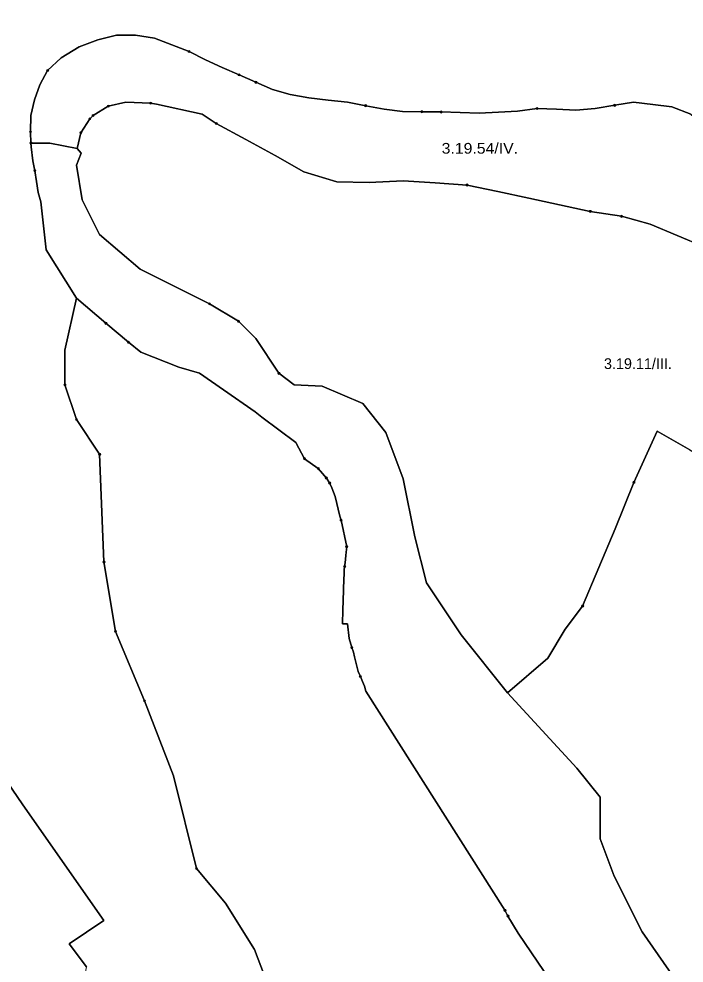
# Model space of a CAD drawing. Extents: x -650455 to -642254, y -1075222 to -1066610.
# Drawn here: x -647324 to -646705, y -1071216 to -1070337 of the extents above; entities that cross this region are included whole.
import ezdxf
from ezdxf.enums import TextEntityAlignment as Align

# ---------------------------------------------------------------- set-up
doc = ezdxf.new("R2010")
doc.units = 0
doc.header["$LTSCALE"] = 4
doc.header["$PDMODE"] = 32
doc.header["$PDSIZE"] = 2
for name, color, linetype, lineweight in [('1', 7, 'Continuous', 25), ('11', 7, 'Continuous', 13), ('12', 7, 'Continuous', 13), ('13', 7, 'Continuous', 13), ('14', 7, 'Continuous', 13), ('15', 7, 'Continuous', 13)]:
    doc.layers.add(name, color=color, linetype=linetype, lineweight=lineweight)
doc.layers.add('2', color=7, linetype='Continuous')

msp = doc.modelspace()

# ---------------------------------------------------------------- linework, layer by layer
at = {"layer": '1'}
for points in [[(-647811.031, -1070119.811), (-647804.895, -1070123.56), (-647767.192, -1070139.719), (-647729.489, -1070139.719), (-647691.786, -1070161.263), (-647681.013, -1070188.194), (-647633.884, -1070234.65), (-647628.498, -1070288.512), (-647606.954, -1070347.759), (-647601.567, -1070433.938), (-647585.409, -1070514.73), (-647558.478, -1070606.295), (-647547.706, -1070654.771), (-647515.389, -1070730.177), (-647460.18, -1070837.227), (-647390.16, -1070966.495), (-647320.14, -1071068.832), (-647244.734, -1071176.555), (-647277.051, -1071198.1), (-647260.893, -1071219.644)], [(-647140.112, -1070434.285), (-647153.326, -1070425.707), (-647195.752, -1070416.202), (-647201.316, -1070415.275), (-647224.499, -1070414.232), (-647240.728, -1070418.173), (-647254.869, -1070426.866), (-647257.883, -1070429.88), (-647266.229, -1070442.863), (-647269.54, -1070457.526), (-647294.977, -1070452.484), (-647312.695, -1070452.484), (-647313.114, -1070441.961), (-647312.695, -1070426.797), (-647309.341, -1070412.193), (-647304.589, -1070398.148), (-647297.182, -1070384.941), (-647284.464, -1070373.132), (-647267.834, -1070363), (-647250.504, -1070356.361), (-647233.175, -1070351.959), (-647215.286, -1070351.889), (-647197.817, -1070354.894), (-647165.534, -1070367.192), (-647150.161, -1070374.949), (-647134.648, -1070382.006), (-647118.996, -1070388.924), (-647103.204, -1070395.842), (-647087.831, -1070402.62), (-647071.34, -1070407.302), (-647053.87, -1070410.446), (-647035.842, -1070412.473), (-647018.093, -1070414.499), (-647001.043, -1070417.644), (-646983.854, -1070420.788), (-646966.664, -1070422.954), (-646948.775, -1070423.304), (-646930.747, -1070423.513), (-646912.999, -1070424.002), (-646895.25, -1070424.491)], [(-646877.361, -1070423.583), (-646895.25, -1070424.491), (-646912.999, -1070424.002), (-646930.747, -1070423.513), (-646948.775, -1070423.304), (-646966.664, -1070422.954), (-646983.854, -1070420.788), (-647001.043, -1070417.644), (-647018.093, -1070414.499), (-647035.842, -1070412.473), (-647053.87, -1070410.446), (-647071.34, -1070407.302), (-647087.831, -1070402.62), (-647103.204, -1070395.842), (-647118.996, -1070388.924), (-647134.648, -1070382.006), (-647150.161, -1070374.949), (-647165.534, -1070367.192), (-647197.817, -1070354.894), (-647215.286, -1070351.889), (-647233.175, -1070351.959), (-647250.504, -1070356.361), (-647267.834, -1070363), (-647284.464, -1070373.132), (-647297.182, -1070384.941), (-647304.589, -1070398.148), (-647309.341, -1070412.193), (-647312.695, -1070426.797), (-647313.114, -1070441.961), (-647312.695, -1070452.484), (-647312.555, -1070456.006), (-647311.018, -1070468.933), (-647309.061, -1070478.227), (-647307.524, -1070488.359), (-647306.126, -1070498.491), (-647303.575, -1070507.298), (-647298.596, -1070551.76), (-647270.318, -1070596.869), (-647281.091, -1070645.345), (-647281.091, -1070677.662)], [(-646966, -1070765.187), (-646982.158, -1070722.098), (-647003.703, -1070695.167), (-647041.406, -1070679.008), (-647067.632, -1070677.48), (-647081.803, -1070666.889), (-647103.347, -1070634.572), (-647119.506, -1070618.414), (-647146.437, -1070602.256), (-647211.071, -1070569.939), (-647248.774, -1070537.621), (-647264.932, -1070505.305), (-647270.318, -1070472.988), (-647265.926, -1070462.007), (-647269.54, -1070457.526), (-647266.229, -1070442.863), (-647257.883, -1070429.88), (-647254.869, -1070426.866), (-647240.728, -1070418.173), (-647224.499, -1070414.232), (-647201.316, -1070415.275), (-647195.752, -1070416.202), (-647153.326, -1070425.707), (-647140.112, -1070434.285), (-647112.756, -1070449.238), (-647085.399, -1070464.192), (-647058.506, -1070479.145), (-647027.904, -1070488.534), (-646997.766, -1070489.346), (-646966.005, -1070487.607), (-646936.33, -1070489.578), (-646906.655, -1070491.548), (-646877.908, -1070497.692), (-646849.161, -1070503.835), (-646791.898, -1070516.123), (-646762.919, -1070520.643), (-646736.258, -1070527.946), (-646710.988, -1070538.494), (-646685.95, -1070549.043)], [(-646895.25, -1070424.491), (-646877.361, -1070423.583), (-646859.613, -1070422.675), (-646841.444, -1070420.229), (-646823.276, -1070420.998), (-646805.248, -1070421.766), (-646787.22, -1070420.299), (-646769.192, -1070417.294), (-646751.583, -1070414.289), (-646733.694, -1070416.456), (-646716.085, -1070418.622), (-646698.336, -1070425.54), (-646690.65, -1070432.527), (-646682.529, -1070440.373)], [(-646698.336, -1070425.54), (-646716.085, -1070418.622), (-646733.694, -1070416.456), (-646751.583, -1070414.289), (-646769.192, -1070417.294), (-646787.22, -1070420.299), (-646805.248, -1070421.766), (-646823.276, -1070420.998), (-646841.444, -1070420.229), (-646859.613, -1070422.675), (-646877.361, -1070423.583)], [(-646685.95, -1070549.043), (-646710.988, -1070538.494), (-646736.258, -1070527.946), (-646762.919, -1070520.643), (-646791.898, -1070516.123), (-646849.161, -1070503.835), (-646877.908, -1070497.692), (-646906.655, -1070491.548), (-646936.33, -1070489.578), (-646966.005, -1070487.607), (-646997.766, -1070489.346), (-647027.904, -1070488.534), (-647058.506, -1070479.145), (-647085.399, -1070464.192), (-647112.756, -1070449.238), (-647140.112, -1070434.285)], [(-647057.986, -1070746.402), (-647066.198, -1070731.193), (-647097.832, -1070707.62), (-647103.915, -1070702.754), (-647133.419, -1070682.375), (-647155.928, -1070666.71), (-647175.09, -1070661.235), (-647210.374, -1070647.091), (-647221.932, -1070637.966), (-647242.919, -1070620.324), (-647270.318, -1070596.869), (-647298.596, -1070551.76), (-647303.575, -1070507.298), (-647306.126, -1070498.491), (-647307.524, -1070488.359), (-647309.061, -1070478.227), (-647311.018, -1070468.933), (-647312.555, -1070456.006), (-647312.695, -1070452.484), (-647294.977, -1070452.484), (-647269.54, -1070457.526)], [(-647269.54, -1070457.526), (-647265.926, -1070462.007), (-647270.318, -1070472.988), (-647264.932, -1070505.305), (-647248.774, -1070537.621), (-647211.071, -1070569.939), (-647146.437, -1070602.256), (-647119.506, -1070618.414), (-647103.347, -1070634.572), (-647081.803, -1070666.889), (-647067.632, -1070677.48), (-647041.406, -1070679.008), (-647003.703, -1070695.167), (-646982.158, -1070722.098), (-646966, -1070765.187), (-646955.228, -1070819.048), (-646944.455, -1070862.138), (-646912.138, -1070910.613), (-646869.049, -1070964.475), (-646804.415, -1071034.495), (-646782.712, -1071061.526), (-646782.712, -1071100.526), (-646769.712, -1071135.193), (-646743.712, -1071187.194), (-646708.811, -1071237.149)], [(-647052.179, -1071341.506), (-647104.694, -1071203.486), (-647131.625, -1071160.397), (-647158.555, -1071128.08), (-647180.1, -1071041.901), (-647207.031, -1070971.881), (-647233.962, -1070907.247), (-647244.734, -1070842.613), (-647248.774, -1070742.296), (-647270.318, -1070709.979), (-647281.091, -1070677.662), (-647281.091, -1070645.345), (-647270.318, -1070596.869), (-647242.919, -1070620.324), (-647221.932, -1070637.966), (-647210.374, -1070647.091), (-647175.09, -1070661.235), (-647155.928, -1070666.71), (-647133.419, -1070682.375), (-647103.915, -1070702.754), (-647097.832, -1070707.62), (-647066.198, -1070731.193), (-647057.986, -1070746.402), (-647045.211, -1070755.527), (-647041.142, -1070760.07), (-647037.657, -1070764.462), (-647034.59, -1070769.039), (-647032.406, -1070773.523), (-647029.479, -1070781.609), (-647025.064, -1070799.849), (-647023.949, -1070803.682), (-647018.744, -1070828.381), (-647019.255, -1070833.353), (-647019.488, -1070836.49), (-647019.813, -1070839.952), (-647020.278, -1070843.414), (-647020.649, -1070846.876), (-647021.021, -1070850.338), (-647021.16, -1070854.358), (-647021.3, -1070858.331)], [(-647281.091, -1070677.662), (-647270.318, -1070709.979), (-647248.774, -1070742.296), (-647244.734, -1070842.613), (-647233.962, -1070907.247), (-647207.031, -1070971.881), (-647180.1, -1071041.901), (-647158.555, -1071128.08), (-647131.625, -1071160.397), (-647104.694, -1071203.486), (-647052.179, -1071341.506)], [(-646699.295, -1070738.147), (-646729.628, -1070720.814), (-646751.296, -1070768.481), (-646768.629, -1070811.815), (-646799.029, -1070883.683), (-646815.187, -1070905.227), (-646831.346, -1070932.158), (-646869.049, -1070964.475), (-646912.138, -1070910.613), (-646944.455, -1070862.138), (-646955.228, -1070819.048), (-646966, -1070765.187)], [(-646708.811, -1071237.149), (-646743.712, -1071187.194), (-646769.712, -1071135.193), (-646782.712, -1071100.526), (-646782.712, -1071061.526), (-646804.415, -1071034.495), (-646869.049, -1070964.475), (-646831.346, -1070932.158), (-646815.187, -1070905.227), (-646799.029, -1070883.683), (-646768.629, -1070811.815), (-646751.296, -1070768.481), (-646729.628, -1070720.814)], [(-646729.628, -1070720.814), (-646699.295, -1070738.147), (-646677.628, -1070751.147), (-646629.961, -1070759.814), (-646586.627, -1070781.481), (-646564.96, -1070798.814), (-646543.293, -1070842.148), (-646499.959, -1070898.482), (-646418.709, -1070853.523)], [(-646834.862, -1071224.003), (-646859.12, -1071188.198), (-646868.599, -1071172.329), (-646871.388, -1071167.008), (-647001.039, -1070962.935), (-647002.154, -1070958.358), (-647003.874, -1070953.78), (-647005.965, -1070949.25), (-647008.195, -1070944.719), (-647011.355, -1070931.033), (-647012.331, -1070926.688), (-647013.958, -1070922.343), (-647016.514, -1070913.979), (-647017.838, -1070900.335), (-647022.768, -1070900.162), (-647022.311, -1070887.151), (-647022.016, -1070878.731), (-647021.3, -1070858.331), (-647021.16, -1070854.358), (-647021.021, -1070850.338), (-647020.649, -1070846.876), (-647020.278, -1070843.414), (-647019.813, -1070839.952), (-647019.488, -1070836.49), (-647019.255, -1070833.353), (-647018.744, -1070828.381), (-647023.949, -1070803.682), (-647025.064, -1070799.849), (-647029.479, -1070781.609), (-647032.406, -1070773.523), (-647034.59, -1070769.039), (-647037.657, -1070764.462), (-647041.142, -1070760.07), (-647045.211, -1070755.527), (-647057.986, -1070746.402)], [(-647260.893, -1071219.644), (-647277.051, -1071198.1), (-647244.734, -1071176.555), (-647320.14, -1071068.832), (-647390.16, -1070966.495), (-647460.18, -1070837.227)], [(-647021.3, -1070858.331), (-647022.016, -1070878.731), (-647022.311, -1070887.151), (-647022.768, -1070900.162), (-647017.838, -1070900.335), (-647016.514, -1070913.979), (-647013.958, -1070922.343), (-647012.331, -1070926.688), (-647011.355, -1070931.033), (-647008.195, -1070944.719), (-647005.965, -1070949.25), (-647003.874, -1070953.78), (-647002.154, -1070958.358), (-647001.039, -1070962.935), (-646871.388, -1071167.008), (-646868.599, -1071172.329), (-646859.12, -1071188.198), (-646834.862, -1071224.003)]]:
    msp.add_lwpolyline(points, dxfattribs=at)
at = {"layer": '11'}
for p, q in [((-647118.996, -1070388.924), (-647103.204, -1070395.842)), ((-647248.774, -1070742.296), (-647270.318, -1070709.979))]:
    msp.add_line(p, q, dxfattribs=at)
for points in [[(-647313.114, -1070441.961), (-647312.695, -1070426.797), (-647309.341, -1070412.193), (-647304.589, -1070398.148), (-647297.182, -1070384.941), (-647284.464, -1070373.132), (-647267.834, -1070363), (-647250.504, -1070356.361), (-647233.175, -1070351.959), (-647215.286, -1070351.889), (-647197.817, -1070354.894), (-647165.534, -1070367.192)], [(-647165.534, -1070367.192), (-647150.161, -1070374.949), (-647134.648, -1070382.006), (-647118.996, -1070388.924)], [(-647103.204, -1070395.842), (-647087.831, -1070402.62), (-647071.34, -1070407.302), (-647053.87, -1070410.446), (-647035.842, -1070412.473), (-647018.093, -1070414.499), (-647001.043, -1070417.644), (-646983.854, -1070420.788), (-646966.664, -1070422.954), (-646948.775, -1070423.304)], [(-646948.775, -1070423.304), (-646930.747, -1070423.513), (-646912.999, -1070424.002), (-646895.25, -1070424.491), (-646877.361, -1070423.583), (-646859.613, -1070422.675), (-646841.444, -1070420.229), (-646823.276, -1070420.998), (-646805.248, -1070421.766), (-646787.22, -1070420.299), (-646769.192, -1070417.294), (-646751.583, -1070414.289), (-646733.694, -1070416.456), (-646716.085, -1070418.622), (-646698.336, -1070425.54)], [(-647270.318, -1070709.979), (-647281.091, -1070677.662), (-647281.091, -1070645.345), (-647270.318, -1070596.869), (-647298.596, -1070551.76), (-647303.575, -1070507.298), (-647306.126, -1070498.491), (-647307.524, -1070488.359), (-647309.061, -1070478.227), (-647311.018, -1070468.933), (-647312.555, -1070456.006), (-647312.695, -1070452.484), (-647313.114, -1070441.961)], [(-647547.706, -1070654.771), (-647515.389, -1070730.177), (-647460.18, -1070837.227), (-647390.16, -1070966.495), (-647320.14, -1071068.832), (-647244.734, -1071176.555), (-647277.051, -1071198.1), (-647260.893, -1071219.644), (-647266.279, -1071246.575), (-647283.784, -1071309.189), (-647287.224, -1071371.123), (-647299.444, -1071388.627), (-647318.899, -1071394.049), (-647345.688, -1071395.963), (-647362.91, -1071400.428), (-647370.883, -1071414.141), (-647371.84, -1071440.612), (-647371.84, -1071461.661)], [(-647207.031, -1070971.881), (-647233.962, -1070907.247), (-647244.734, -1070842.613), (-647248.774, -1070742.296)], [(-646992.931, -1071454.616), (-647052.179, -1071341.506), (-647104.694, -1071203.486), (-647131.625, -1071160.397), (-647158.555, -1071128.08), (-647180.1, -1071041.901), (-647207.031, -1070971.881)]]:
    msp.add_lwpolyline(points, dxfattribs=at)
for p in [(-647165.534, -1070367.192), (-647118.996, -1070388.924), (-647103.204, -1070395.842), (-646948.775, -1070423.304), (-647313.114, -1070441.961), (-647270.318, -1070709.979), (-647248.774, -1070742.296), (-647207.031, -1070971.881)]:
    msp.add_point(p, dxfattribs=at)
at = {"layer": '12'}
msp.add_lwpolyline([(-647283.784, -1071309.189), (-647266.279, -1071246.575), (-647260.893, -1071219.644), (-647277.051, -1071198.1), (-647244.734, -1071176.555), (-647320.14, -1071068.832), (-647390.16, -1070966.495), (-647460.18, -1070837.227), (-647515.389, -1070730.177), (-647547.706, -1070654.771), (-647558.478, -1070606.295), (-647585.409, -1070514.73), (-647601.567, -1070433.938), (-647606.954, -1070347.759), (-647628.498, -1070288.512)], dxfattribs=at)
at = {"layer": '13'}
for p, q in [((-647257.883, -1070429.88), (-647266.229, -1070442.863)), ((-647146.437, -1070602.256), (-647119.506, -1070618.414))]:
    msp.add_line(p, q, dxfattribs=at)
for points in [[(-646906.655, -1070491.548), (-646936.33, -1070489.578), (-646966.005, -1070487.607), (-646997.766, -1070489.346), (-647027.904, -1070488.534), (-647058.506, -1070479.145), (-647085.399, -1070464.192), (-647112.756, -1070449.238), (-647140.112, -1070434.285), (-647153.326, -1070425.707), (-647195.752, -1070416.202), (-647201.316, -1070415.275), (-647224.499, -1070414.232), (-647240.728, -1070418.173), (-647254.869, -1070426.866), (-647257.883, -1070429.88)], [(-647266.229, -1070442.863), (-647269.54, -1070457.526), (-647265.926, -1070462.007), (-647270.318, -1070472.988), (-647264.932, -1070505.305), (-647248.774, -1070537.621), (-647211.071, -1070569.939), (-647146.437, -1070602.256)], [(-646762.919, -1070520.643), (-646791.898, -1070516.123), (-646849.161, -1070503.835), (-646877.908, -1070497.692), (-646906.655, -1070491.548)], [(-646632.165, -1070565.271), (-646660.912, -1070559.591), (-646685.95, -1070549.043), (-646710.988, -1070538.494), (-646736.258, -1070527.946), (-646762.919, -1070520.643)], [(-647119.506, -1070618.414), (-647103.347, -1070634.572), (-647081.803, -1070666.889)], [(-647081.803, -1070666.889), (-647067.632, -1070677.48), (-647041.406, -1070679.008), (-647003.703, -1070695.167), (-646982.158, -1070722.098), (-646966, -1070765.187), (-646955.228, -1070819.048), (-646944.455, -1070862.138), (-646912.138, -1070910.613), (-646869.049, -1070964.475), (-646831.346, -1070932.158), (-646815.187, -1070905.227), (-646799.029, -1070883.683)], [(-646677.628, -1070751.147), (-646699.295, -1070738.147), (-646729.628, -1070720.814), (-646751.296, -1070768.481), (-646768.629, -1070811.815), (-646799.029, -1070883.683), (-646815.187, -1070905.227), (-646831.346, -1070932.158), (-646869.049, -1070964.475), (-646804.415, -1071034.495), (-646782.712, -1071061.526), (-646782.712, -1071100.526), (-646769.712, -1071135.193), (-646743.712, -1071187.194), (-646708.811, -1071237.149)], [(-646751.296, -1070768.481), (-646729.628, -1070720.814), (-646699.295, -1070738.147)], [(-646799.029, -1070883.683), (-646768.629, -1070811.815), (-646751.296, -1070768.481)]]:
    msp.add_lwpolyline(points, dxfattribs=at)
for p in [(-647257.883, -1070429.88), (-647266.229, -1070442.863), (-646906.655, -1070491.548), (-646762.919, -1070520.643), (-647146.437, -1070602.256), (-647119.506, -1070618.414), (-647081.803, -1070666.889), (-646751.296, -1070768.481), (-646799.029, -1070883.683)]:
    msp.add_point(p, dxfattribs=at)
at = {"layer": '14'}
for p, q in [((-647254.869, -1070426.866), (-647240.728, -1070418.173)), ((-647257.883, -1070429.88), (-647254.869, -1070426.866)), ((-646791.898, -1070516.123), (-646762.919, -1070520.643)), ((-647244.734, -1070842.613), (-647233.962, -1070907.247))]:
    msp.add_line(p, q, dxfattribs=at)
for points in [[(-647001.043, -1070417.644), (-647018.093, -1070414.499), (-647035.842, -1070412.473), (-647053.87, -1070410.446), (-647071.34, -1070407.302), (-647087.831, -1070402.62), (-647103.204, -1070395.842), (-647118.996, -1070388.924), (-647134.648, -1070382.006), (-647150.161, -1070374.949), (-647165.534, -1070367.192), (-647197.817, -1070354.894), (-647215.286, -1070351.889), (-647233.175, -1070351.959), (-647250.504, -1070356.361), (-647267.834, -1070363), (-647284.464, -1070373.132), (-647297.182, -1070384.941)], [(-647297.182, -1070384.941), (-647304.589, -1070398.148), (-647309.341, -1070412.193), (-647312.695, -1070426.797), (-647313.114, -1070441.961), (-647312.695, -1070452.484)], [(-647240.728, -1070418.173), (-647224.499, -1070414.232), (-647201.316, -1070415.275)], [(-647201.316, -1070415.275), (-647195.752, -1070416.202), (-647153.326, -1070425.707), (-647140.112, -1070434.285)], [(-646514.69, -1070497.343), (-646513.93, -1070496.996), (-646504.412, -1070489.744), (-646522.293, -1070490.738), (-646540.7, -1070486.685), (-646578.106, -1070489.302), (-646592.291, -1070489.809), (-646643.714, -1070491.413), (-646664.401, -1070487.107), (-646680.613, -1070473.935), (-646689.056, -1070460.931), (-646689.394, -1070455.19), (-646688.291, -1070450.623), (-646683.243, -1070441.891), (-646682.529, -1070440.373), (-646690.65, -1070432.527), (-646698.336, -1070425.54), (-646716.085, -1070418.622), (-646733.694, -1070416.456), (-646751.583, -1070414.289), (-646769.192, -1070417.294)], [(-646930.747, -1070423.513), (-646948.775, -1070423.304), (-646966.664, -1070422.954), (-646983.854, -1070420.788), (-647001.043, -1070417.644)], [(-646841.444, -1070420.229), (-646859.613, -1070422.675), (-646877.361, -1070423.583), (-646895.25, -1070424.491), (-646912.999, -1070424.002), (-646930.747, -1070423.513)], [(-646769.192, -1070417.294), (-646787.22, -1070420.299), (-646805.248, -1070421.766), (-646823.276, -1070420.998), (-646841.444, -1070420.229)], [(-647312.695, -1070452.484), (-647294.977, -1070452.484), (-647269.54, -1070457.526), (-647266.229, -1070442.863), (-647257.883, -1070429.88)], [(-647140.112, -1070434.285), (-647112.756, -1070449.238), (-647085.399, -1070464.192), (-647058.506, -1070479.145), (-647027.904, -1070488.534), (-646997.766, -1070489.346), (-646966.005, -1070487.607), (-646936.33, -1070489.578), (-646906.655, -1070491.548), (-646877.908, -1070497.692), (-646849.161, -1070503.835), (-646791.898, -1070516.123)], [(-646762.919, -1070520.643), (-646736.258, -1070527.946), (-646710.988, -1070538.494), (-646685.95, -1070549.043)], [(-647242.919, -1070620.324), (-647270.318, -1070596.869), (-647281.091, -1070645.345), (-647281.091, -1070677.662)], [(-647057.986, -1070746.402), (-647066.198, -1070731.193), (-647097.832, -1070707.62), (-647103.915, -1070702.754), (-647133.419, -1070682.375), (-647155.928, -1070666.71), (-647175.09, -1070661.235), (-647210.374, -1070647.091), (-647221.932, -1070637.966), (-647242.919, -1070620.324)], [(-647281.091, -1070677.662), (-647270.318, -1070709.979), (-647248.774, -1070742.296), (-647244.734, -1070842.613)], [(-647023.949, -1070803.682), (-647025.064, -1070799.849), (-647029.479, -1070781.609), (-647032.406, -1070773.523), (-647034.59, -1070769.039), (-647037.657, -1070764.462), (-647041.142, -1070760.07), (-647045.211, -1070755.527), (-647057.986, -1070746.402)], [(-647020.649, -1070846.876), (-647020.278, -1070843.414), (-647019.813, -1070839.952), (-647019.488, -1070836.49), (-647019.255, -1070833.353), (-647018.744, -1070828.381), (-647023.949, -1070803.682)], [(-647005.965, -1070949.25), (-647008.195, -1070944.719), (-647011.355, -1070931.033), (-647012.331, -1070926.688), (-647013.958, -1070922.343), (-647016.514, -1070913.979), (-647017.838, -1070900.335), (-647022.768, -1070900.162), (-647022.311, -1070887.151), (-647022.016, -1070878.731), (-647021.3, -1070858.331), (-647021.16, -1070854.358), (-647021.021, -1070850.338), (-647020.649, -1070846.876)], [(-647233.962, -1070907.247), (-647207.031, -1070971.881), (-647180.1, -1071041.901), (-647158.555, -1071128.08)], [(-646871.388, -1071167.008), (-647001.039, -1070962.935), (-647002.154, -1070958.358), (-647003.874, -1070953.78), (-647005.965, -1070949.25)], [(-647158.555, -1071128.08), (-647131.625, -1071160.397), (-647104.694, -1071203.486), (-647052.179, -1071341.506), (-646992.931, -1071454.616), (-646885.208, -1071621.587)], [(-646829.299, -1071242.546), (-646824.502, -1071239.296), (-646834.862, -1071224.003), (-646859.12, -1071188.198), (-646868.599, -1071172.329), (-646871.388, -1071167.008)]]:
    msp.add_lwpolyline(points, dxfattribs=at)
for p in [(-647297.182, -1070384.941), (-647201.316, -1070415.275), (-646769.192, -1070417.294), (-647240.728, -1070418.173), (-647001.043, -1070417.644), (-646930.747, -1070423.513), (-646841.444, -1070420.229), (-647257.883, -1070429.88), (-647254.869, -1070426.866), (-647140.112, -1070434.285), (-647312.695, -1070452.484), (-646791.898, -1070516.123), (-646762.919, -1070520.643), (-647242.919, -1070620.324), (-647281.091, -1070677.662), (-647057.986, -1070746.402), (-647023.949, -1070803.682), (-647244.734, -1070842.613), (-647020.649, -1070846.876), (-647233.962, -1070907.247), (-647005.965, -1070949.25), (-647158.555, -1071128.08), (-646871.388, -1071167.008)]:
    msp.add_point(p, dxfattribs=at)
at = {"layer": '15'}
msp.add_line((-647037.657, -1070764.462), (-647034.59, -1070769.039), dxfattribs=at)
for points in [[(-646708.811, -1071237.149), (-646743.712, -1071187.194), (-646769.712, -1071135.193), (-646782.712, -1071100.526), (-646782.712, -1071061.526), (-646804.415, -1071034.495), (-646869.049, -1070964.475), (-646912.138, -1070910.613), (-646944.455, -1070862.138), (-646955.228, -1070819.048), (-646966, -1070765.187), (-646982.158, -1070722.098), (-647003.703, -1070695.167), (-647041.406, -1070679.008), (-647067.632, -1070677.48), (-647081.803, -1070666.889), (-647103.347, -1070634.572), (-647119.506, -1070618.414), (-647146.437, -1070602.256), (-647211.071, -1070569.939), (-647248.774, -1070537.621), (-647264.932, -1070505.305), (-647270.318, -1070472.988), (-647265.926, -1070462.007), (-647269.54, -1070457.526), (-647294.977, -1070452.484), (-647312.695, -1070452.484)], [(-647312.695, -1070452.484), (-647312.555, -1070456.006), (-647311.018, -1070468.933), (-647309.061, -1070478.227)], [(-647309.061, -1070478.227), (-647307.524, -1070488.359), (-647306.126, -1070498.491), (-647303.575, -1070507.298), (-647298.596, -1070551.76), (-647270.318, -1070596.869), (-647242.919, -1070620.324), (-647221.932, -1070637.966)], [(-647221.932, -1070637.966), (-647210.374, -1070647.091), (-647175.09, -1070661.235), (-647155.928, -1070666.71), (-647133.419, -1070682.375), (-647103.915, -1070702.754), (-647097.832, -1070707.62), (-647066.198, -1070731.193), (-647057.986, -1070746.402), (-647045.211, -1070755.527)], [(-647045.211, -1070755.527), (-647041.142, -1070760.07), (-647037.657, -1070764.462)], [(-647034.59, -1070769.039), (-647032.406, -1070773.523), (-647029.479, -1070781.609), (-647025.064, -1070799.849), (-647023.949, -1070803.682), (-647018.744, -1070828.381)], [(-647018.744, -1070828.381), (-647019.255, -1070833.353), (-647019.488, -1070836.49), (-647019.813, -1070839.952), (-647020.278, -1070843.414), (-647020.649, -1070846.876), (-647021.021, -1070850.338), (-647021.16, -1070854.358), (-647021.3, -1070858.331), (-647022.016, -1070878.731), (-647022.311, -1070887.151), (-647022.768, -1070900.162), (-647017.838, -1070900.335), (-647016.514, -1070913.979), (-647013.958, -1070922.343)], [(-647013.958, -1070922.343), (-647012.331, -1070926.688), (-647011.355, -1070931.033), (-647008.195, -1070944.719), (-647005.965, -1070949.25), (-647003.874, -1070953.78), (-647002.154, -1070958.358), (-647001.039, -1070962.935), (-646871.388, -1071167.008), (-646868.599, -1071172.329)], [(-646868.599, -1071172.329), (-646859.12, -1071188.198), (-646834.862, -1071224.003)]]:
    msp.add_lwpolyline(points, dxfattribs=at)
for p in [(-647312.695, -1070452.484), (-647309.061, -1070478.227), (-647221.932, -1070637.966), (-647045.211, -1070755.527), (-647037.657, -1070764.462), (-647034.59, -1070769.039), (-647018.744, -1070828.381), (-647013.958, -1070922.343), (-646868.599, -1071172.329)]:
    msp.add_point(p, dxfattribs=at)

# ---------------------------------------------------------------- texts
at = {"layer": '2', "width": 1.1}
msp.add_text('3.19.54/IV.', height=10, dxfattribs=at).set_placement((-646894.736, -1070462.35), align=Align.CENTER)
at = {"layer": '2'}
msp.add_text('3.19.11/III.', height=10, dxfattribs=at).set_placement((-646747.586, -1070662.908), align=Align.CENTER)

doc.saveas('drawing.dxf')
